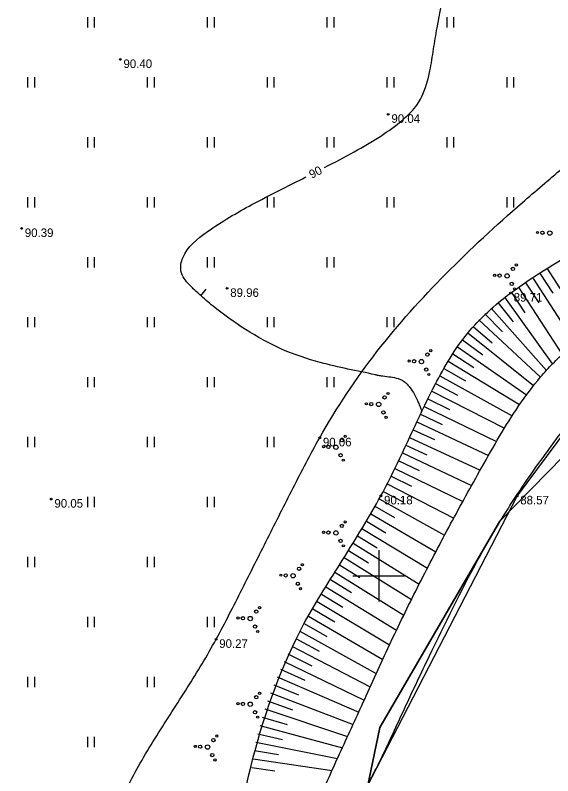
# Model space of a CAD drawing. Extents: x 635228 to 635525, y 248590 to 248800.
# Drawn here: x 635378.76 to 635410.17, y 248638.32 to 248682.72 of the extents above; entities that cross this region are included whole.
import ezdxf

# ---------------------------------------------------------------- set-up
doc = ezdxf.new("R2010")
doc.units = 0
for name, color, linetype in [('GEOD_ELEM_####_####_#', 7, 'Continuous'), ('HIDG_GRAV_####_####_#', 7, 'Continuous'), ('RAMI_UZMR_####_####_#', 7, 'Continuous'), ('RELJ_AATZ_####_TKST_#', 7, 'Continuous'), ('RELJ_ELEM_####_####_#', 7, 'Continuous'), ('RELJ_HORZ_####_TKST_#', 7, 'Continuous'), ('RELJ_HORZ_RESN_####_#', 7, 'Continuous'), ('RELJ_NOGA_####_####_#', 7, 'Continuous'), ('ROBZ_UZMR_####_####_#', 7, 'Continuous'), ('TERT_ELEM_####_####_#', 7, 'Continuous'), ('TERT_KONT_####_####_#', 7, 'Continuous')]:
    doc.layers.add(name, color=color, linetype=linetype)

msp = doc.modelspace()

# ---------------------------------------------------------------- linework, layer by layer
at = {"layer": 'GEOD_ELEM_####_####_#'}
for p, q in [((635400, 248651.5), (635400, 248650)), ((635398.5, 248650), (635400, 248650)), ((635400, 248650), (635400, 248648.5)), ((635400, 248650), (635401.5, 248650))]:
    msp.add_line(p, q, dxfattribs=at)
at = {"layer": 'HIDG_GRAV_####_####_#'}
for points in [[(635394.244, 248623.295), (635394.9074355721, 248630.6631552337), (635396.5650242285, 248636.944974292), (635397.8888882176, 248639.97580624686), (635399.2686043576, 248642.98780740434), (635400.0423829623, 248644.69884236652), (635400.835233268, 248646.3905777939), (635402.4795660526, 248649.72803076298), (635404.20443685, 248653.0239277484), (635406.0126797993, 248656.30203018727), (635407.0670223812, 248658.14081276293), (635408.1930324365, 248659.92698593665), (635409.4621962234, 248661.60192368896), (635410.172800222, 248662.37935865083), (635410.946, 248663.10700000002), (635413.0008032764, 248664.6744257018), (635415.1640977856, 248666.05372522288), (635417.3478434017, 248667.38916213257), (635419.464, 248668.825), (635422.2083511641, 248670.85354035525), (635424.965867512, 248672.86854694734), (635430.4558647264, 248676.93578902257), (635435.8049295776, 248681.1823865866), (635438.3862804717, 248683.4215875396), (635439.6466024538, 248684.57867623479), (635440.8840000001, 248685.76400000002), (635443.6087249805, 248688.6747140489), (635446.1599310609, 248691.73220612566), (635448.6719216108, 248694.81834513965), (635451.279, 248697.815), (635453.9336502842, 248700.48189136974), (635456.6811388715, 248703.07136968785), (635459.3523080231, 248705.7266631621), (635461.7780000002, 248708.59100000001), (635461.778, 248708.59100000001)], [(635396.7397638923, 248625.2320466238), (635397.9986579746, 248634.27312358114), (635398.9188026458, 248636.96227546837), (635399.5920874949, 248638.24717771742), (635399.9292604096, 248638.88899780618), (635400.2466831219, 248639.53584001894), (635401.591165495, 248642.41958219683), (635402.9524948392, 248645.2868638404), (635405.8217854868, 248650.96088254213), (635407.5583128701, 248653.91205967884), (635409.4799859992, 248656.7354955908), (635411.5283407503, 248659.48290512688), (635413.6449129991, 248662.20600313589), (635414.8182615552, 248663.6538935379), (635415.4704678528, 248664.3057478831), (635416.2076616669, 248664.85985159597), (635417.1601741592, 248665.41138033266), (635418.1313630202, 248665.91742947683), (635419.1067857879, 248666.41122678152), (635420.072, 248666.926), (635421.5645353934, 248667.7418115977), (635423.0692260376, 248668.5354410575), (635426.0762392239, 248670.12612318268), (635429.0153718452, 248671.8379856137), (635430.4352117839, 248672.78309045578), (635431.128452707, 248673.2855892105), (635431.8089561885, 248673.81096758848), (635433.1953696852, 248675.0040709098), (635434.526751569, 248676.2563297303), (635437.0226234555, 248678.92292892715), (635441.762, 248684.467), (635443.1273679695, 248686.0473501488), (635444.4678763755, 248687.6485508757), (635447.1219662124, 248690.87245996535), (635449.819572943, 248694.05663907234), (635451.2144774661, 248695.60817732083), (635452.6560000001, 248697.119), (635458.0231966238, 248702.2419696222), (635463.584, 248707.15000000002)]]:
    msp.add_spline(points, degree=3, dxfattribs=at)
at = {"layer": 'RAMI_UZMR_####_####_#'}
msp.add_lwpolyline([(635426.003, 248728.15499999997), (635436.69, 248722.584), (635450.108, 248715.45700000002), (635458.287, 248711.34600000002), (635461.7780000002, 248708.59100000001), (635463.584, 248707.15000000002), (635452.6560000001, 248697.119), (635441.762, 248684.467), (635435.9528772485, 248677.73413872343), (635432.018527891, 248673.97985762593), (635429.363741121, 248672.06248825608), (635427.0556775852, 248670.66460585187), (635420.072, 248666.926), (635415.05332695, 248664.00973325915), (635408.095218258, 248654.65947737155), (635398.6701763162, 248636.43948679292), (635398.046283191, 248634.41686083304), (635396.3166782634, 248622.87374513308), (635394.244, 248623.295), (635390.206, 248622.483), (635381.566, 248626.41900000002), (635379.918, 248627.738), (635364.657, 248634.36500000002)], dxfattribs=at)
at = {"layer": 'RELJ_ELEM_####_####_#'}
for centre in [(635384.9030000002, 248680.138), (635400.561, 248676.937), (635379.1390000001, 248670.27300000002), (635391.143, 248666.77500000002), (635407.706, 248666.499), (635396.556, 248658.053), (635380.869, 248654.47400000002), (635400.128, 248654.662), (635408.0881315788, 248654.66319467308), (635390.4990000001, 248646.29)]:
    msp.add_circle(centre, 0.05, dxfattribs=at)
at = {"layer": 'RELJ_HORZ_RESN_####_#'}
msp.add_line((635389.603708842, 248666.34758500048), (635389.9254290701, 248666.7303330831), dxfattribs=at)
for points in [[(635396.8403365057, 248673.83023932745), (635398.5699520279, 248674.74721849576), (635400.1196081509, 248675.6687893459), (635401.3847631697, 248676.59316814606), (635401.8779834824, 248677.05585311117), (635402.2608753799, 248677.51857116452), (635402.5005008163, 248677.92779942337), (635402.9962003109, 248679.47940420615), (635403.1093939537, 248680.10527297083), (635403.2077718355, 248680.73304831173), (635403.3050539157, 248681.36081107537), (635403.4149601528, 248681.98664210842), (635403.9947087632, 248684.49620174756), (635404.4941894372, 248685.58182624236), (635404.822447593, 248686.0525951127), (635405.213, 248686.464), (635405.5227683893, 248686.49325254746), (635405.8948771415, 248686.27621660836), (635406.269797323, 248686.04907236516), (635406.588, 248686.048), (635407.1331532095, 248686.47133617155), (635407.6549224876, 248686.94769115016), (635408.6437981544, 248688.02779111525), (635410.511320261, 248690.47588617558), (635412.43838879, 248692.8856225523), (635414.0718482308, 248694.36296271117), (635414.672826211, 248694.7503376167), (635415.8418707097, 248695.38166460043), (635417.0157559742, 248695.99905223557), (635418.2014500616, 248696.5900310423), (635419.4059210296, 248697.14213154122), (635424.3998390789, 248699.29274669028), (635429.4588912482, 248701.50672660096), (635434.3873884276, 248704.0886148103), (635435.2434356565, 248704.60530447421), (635437.7315604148, 248706.27775516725), (635439.1970704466, 248707.5552960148), (635439.8338858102, 248708.26101524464), (635440.1227716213, 248708.63326282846), (635440.3898668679, 248709.01944554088), (635440.6922176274, 248709.6864690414), (635440.8034457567, 248710.32396866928)], [(635399.8103222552, 248661.73440351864), (635396.5888085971, 248662.45061356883), (635394.366626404, 248663.21189688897), (635392.2183961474, 248664.3772104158), (635390.3210872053, 248665.73618021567), (635389.5218311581, 248666.4225443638), (635389.1692307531, 248666.7559414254), (635389.005897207, 248666.91875560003), (635388.851668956, 248667.07843235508), (635388.580502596, 248667.44246406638), (635388.4463483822, 248667.81035988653), (635388.5518971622, 248668.55710948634), (635389.9981689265, 248670.08999995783), (635392.5956165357, 248671.66695390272), (635394.140135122, 248672.46878284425), (635395.7493722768, 248673.27782145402)], [(635399.8103222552, 248661.73440351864), (635400.0261478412, 248661.69119462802), (635400.2502143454, 248661.65879397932), (635400.7032919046, 248661.6004776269), (635401.1299985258, 248661.5075749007), (635401.3211013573, 248661.43194128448), (635401.4089269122, 248661.38399174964), (635401.4506378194, 248661.35712915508), (635401.4709090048, 248661.3429315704), (635401.4907778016, 248661.32820623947), (635401.5807723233, 248661.25417038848), (635401.6657716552, 248661.17358317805), (635401.8221621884, 248660.99456123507), (635402.0901527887, 248660.5777731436), (635402.316788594, 248660.10674684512), (635402.4214856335, 248659.8599271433), (635402.524108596, 248659.61038721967)]]:
    msp.add_spline(points, degree=3, dxfattribs=at)
at = {"layer": 'RELJ_NOGA_####_####_#'}
for p, q in [((635409.8625812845, 248667.8947613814), (635412.2588250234, 248664.15017364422)), ((635409.0209685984, 248667.3546810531), (635411.471024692, 248663.54545166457)), ((635409.4414942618, 248667.62515871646), (635410.1688320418, 248666.49432891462)), ((635408.1819740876, 248666.81054345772), (635410.7270639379, 248662.91267369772)), ((635408.6011266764, 248667.08314360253), (635409.349370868, 248665.9286690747)), ((635407.7635920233, 248666.53676212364), (635408.5437852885, 248665.3468685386)), ((635406.954140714, 248665.95034267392), (635407.8639578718, 248664.8211765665)), ((635407.351260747, 248666.25404517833), (635410.1500262, 248662.3558521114)), ((635406.5727376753, 248665.62711643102), (635409.80308503, 248661.98852616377)), ((635406.2075806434, 248665.28563474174), (635407.2351275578, 248664.23948709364)), ((635405.858323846, 248664.92789740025), (635409.4538366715, 248661.59191409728)), ((635405.2067690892, 248664.16964832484), (635409.0494359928, 248661.09846031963)), ((635405.524936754, 248664.55531519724), (635406.6406852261, 248663.590880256)), ((635404.9031081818, 248663.7724541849), (635406.0924224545, 248662.89991224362)), ((635404.6129288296, 248663.36530031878), (635408.6437325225, 248660.56488204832)), ((635404.3355010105, 248662.94934938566), (635405.570150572, 248662.1538915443)), ((635404.0695322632, 248662.5259769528), (635408.2372923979, 248659.99157579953)), ((635403.8138835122, 248662.09628868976), (635405.0757899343, 248661.3683422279)), ((635403.5677171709, 248661.6610947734), (635407.7993181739, 248659.3316462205)), ((635403.3298174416, 248661.2213252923), (635404.6019012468, 248660.54583964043)), ((635403.0989996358, 248660.77779578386), (635407.3504701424, 248658.61333582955)), ((635402.8744485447, 248660.33105999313), (635404.1476621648, 248659.69996200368)), ((635402.6546938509, 248659.88194460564), (635406.8895087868, 248657.83840831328)), ((635402.4388250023, 248659.43094679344), (635403.7045318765, 248658.83309198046)), ((635402.2259600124, 248658.9785223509), (635406.4163447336, 248657.0153306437)), ((635402.0149403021, 248658.5252339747), (635403.2638939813, 248657.9460922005)), ((635401.8047126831, 248658.07157734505), (635405.9324446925, 248656.15963557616)), ((635401.5944158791, 248657.61795289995), (635402.8209429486, 248657.04721503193)), ((635401.3828817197, 248657.16490453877), (635405.4323121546, 248655.26686429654)), ((635401.1693375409, 248656.7128007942), (635402.371857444, 248656.14133387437)), ((635400.9523629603, 248656.26233404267), (635404.9155535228, 248654.3321689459)), ((635400.7312182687, 248655.813900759), (635401.9090420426, 248655.22776486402)), ((635400.504525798, 248655.3682482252), (635404.3841950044, 248653.35689460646)), ((635400.2715566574, 248654.92584629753), (635401.4244992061, 248654.3050520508)), ((635400.0311495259, 248654.487441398), (635403.8529759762, 248652.36697469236)), ((635399.7853263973, 248654.05204713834), (635400.927641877, 248653.39941430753)), ((635399.5353194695, 248653.61904068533), (635403.3432881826, 248651.40158427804)), ((635399.2814918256, 248653.18826239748), (635400.4250526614, 248652.50846256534)), ((635399.0245691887, 248652.7593226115), (635402.8491060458, 248650.44987386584)), ((635398.7651660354, 248652.33187755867), (635399.9195401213, 248651.6292315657)), ((635398.5036220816, 248651.90573880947), (635402.372303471, 248649.51638393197)), ((635398.2406116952, 248651.48050329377), (635399.4107770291, 248650.7538052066)), ((635397.9767011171, 248651.05582561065), (635401.9139812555, 248648.60379598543)), ((635397.7123818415, 248650.63140209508), (635398.9059240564, 248649.88809687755)), ((635397.4480625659, 248650.2069785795), (635401.4691463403, 248647.70275835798)), ((635397.1841714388, 248649.7822890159), (635398.404886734, 248649.02542891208)), ((635396.9214185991, 248649.35689421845), (635401.0455520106, 248646.82971114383)), ((635396.6603968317, 248648.9304351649), (635397.912700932, 248648.16809362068)), ((635396.4015071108, 248648.5026791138), (635400.6297667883, 248645.95755458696)), ((635396.1453199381, 248648.07329945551), (635397.4305159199, 248647.310845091)), ((635395.8924346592, 248647.64196741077), (635400.2341078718, 248645.11319087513)), ((635395.6434494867, 248647.2083733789), (635396.9638008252, 248646.45688244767)), ((635395.3987285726, 248646.77235914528), (635399.8578038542, 248644.2959553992)), ((635395.1592577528, 248646.33343967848), (635396.515748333, 248645.60547558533)), ((635394.9254901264, 248645.89145760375), (635399.5018986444, 248643.51020417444)), ((635394.6980998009, 248645.44616223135), (635396.0872204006, 248644.74903596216)), ((635394.4778019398, 248644.99731716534), (635399.1602100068, 248642.7450621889)), ((635394.2652962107, 248644.54473257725), (635395.6844547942, 248643.8953250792)), ((635394.0612347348, 248644.08827897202), (635398.8356996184, 248642.02842921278)), ((635393.8665220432, 248643.6277600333), (635395.3065858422, 248643.03745984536)), ((635393.6819048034, 248643.1631041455), (635398.5056898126, 248641.3108477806)), ((635393.5081369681, 248642.69428455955), (635394.9604265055, 248642.1775982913)), ((635393.3459706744, 248642.2213274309), (635398.1849883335, 248640.61727893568)), ((635393.1963722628, 248641.74424806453), (635394.6486151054, 248641.31022044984)), ((635393.0598719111, 248641.26325946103), (635397.8804933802, 248639.9573297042)), ((635392.9373423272, 248640.77852435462), (635394.378894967, 248640.44188390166)), ((635392.8295318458, 248640.2903059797), (635397.5937404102, 248639.32973477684)), ((635392.736983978, 248639.79896699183), (635394.1504539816, 248639.56165782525)), ((635392.6599254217, 248639.30495737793), (635397.2803028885, 248638.63095366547)), ((635392.5877511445, 248638.81019392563), (635393.9330397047, 248638.61394816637))]:
    msp.add_line(p, q, dxfattribs=at)
msp.add_spline([(635390.206, 248622.483), (635392.6761559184, 248639.41621940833), (635395.6724652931, 248647.2597307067), (635397.9131924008, 248650.95381667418), (635399.048256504, 248652.79837067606), (635400.128, 248654.662), (635400.9493075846, 248656.2558432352), (635403.3016292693, 248661.16811378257), (635405.1862207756, 248664.14373210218), (635407.706, 248666.499), (635412.1610828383, 248669.3503906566), (635416.627, 248672.168), (635424.6828055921, 248677.31078055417), (635432.728, 248682.47600000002), (635436.7060689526, 248685.70428438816), (635438.5008534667, 248687.5575466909), (635440.2150000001, 248689.48700000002), (635442.5291182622, 248692.3528262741), (635444.7219287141, 248695.30565037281), (635446.9190248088, 248698.24939928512), (635449.246, 248701.08800000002), (635451.3600052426, 248703.48451832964), (635453.4937434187, 248705.86484004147), (635457.9500000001, 248710.44), (635458.6576193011, 248711.10744185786)], degree=3, dxfattribs=at)
at = {"layer": 'ROBZ_UZMR_####_####_#'}
msp.add_lwpolyline([(635325.5420000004, 248659.74000000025), (635329.6529999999, 248676.3660000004), (635327.79, 248676.82799999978), (635337.4600999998, 248688.65990000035), (635343.3430000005, 248703.1199999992), (635360.483, 248762.61500000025), (635458.6069999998, 248711.13399999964), (635465.4589999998, 248707.53900000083), (635439.4570000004, 248681.03800000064), (635424.5429999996, 248670.01400000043), (635420.9790000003, 248667.37900000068), (635407.0700000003, 248653.17999999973), (635400.0669999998, 248641.1490000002), (635395.1619999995, 248617.53900000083), (635389.0310000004, 248621.06200000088), (635375.858, 248629.11500000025)], close=True, dxfattribs=at)
msp.add_lwpolyline([(635432.3373132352, 248596.18186087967), (635395.1619999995, 248617.53900000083), (635400.0669999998, 248641.1490000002), (635407.0700000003, 248653.17999999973), (635420.9790000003, 248667.37900000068), (635424.5429999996, 248670.01400000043), (635430.9589999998, 248667.77300000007), (635522.3373132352, 248635.85405923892)], dxfattribs=at)
at = {"layer": 'TERT_ELEM_####_####_#'}
for p, q in [((635383, 248682), (635383, 248682.6)), ((635383.4, 248682), (635383.4, 248682.6)), ((635390, 248682), (635390, 248682.6)), ((635390.4, 248682), (635390.4, 248682.6)), ((635397, 248682), (635397, 248682.6)), ((635397.4, 248682), (635397.4, 248682.6)), ((635404, 248682), (635404, 248682.6)), ((635404.4, 248682), (635404.4, 248682.6)), ((635379.5, 248678.5), (635379.5, 248679.1)), ((635379.9, 248678.5), (635379.9, 248679.1)), ((635386.5, 248678.5), (635386.5, 248679.1)), ((635386.9, 248678.5), (635386.9, 248679.1)), ((635393.5, 248678.5), (635393.5, 248679.1)), ((635393.9, 248678.5), (635393.9, 248679.1)), ((635400.5, 248678.5), (635400.5, 248679.1)), ((635400.9, 248678.5), (635400.9, 248679.1)), ((635407.5, 248678.5), (635407.5, 248679.1)), ((635407.9, 248678.5), (635407.9, 248679.1)), ((635383, 248675), (635383, 248675.6)), ((635383.4, 248675), (635383.4, 248675.6)), ((635390, 248675), (635390, 248675.6)), ((635390.4, 248675), (635390.4, 248675.6)), ((635397, 248675), (635397, 248675.6)), ((635397.4, 248675), (635397.4, 248675.6)), ((635404, 248675), (635404, 248675.6)), ((635404.4, 248675), (635404.4, 248675.6)), ((635379.5, 248671.5), (635379.5, 248672.1)), ((635379.9, 248671.5), (635379.9, 248672.1)), ((635386.5, 248671.5), (635386.5, 248672.1)), ((635386.9, 248671.5), (635386.9, 248672.1)), ((635393.5, 248671.5), (635393.5, 248672.1)), ((635393.9, 248671.5), (635393.9, 248672.1)), ((635400.5, 248671.5), (635400.5, 248672.1)), ((635400.9, 248671.5), (635400.9, 248672.1)), ((635407.5, 248671.5), (635407.5, 248672.1)), ((635407.9, 248671.5), (635407.9, 248672.1)), ((635383, 248668), (635383, 248668.6)), ((635383.4, 248668), (635383.4, 248668.6)), ((635390, 248668), (635390, 248668.6)), ((635390.4, 248668), (635390.4, 248668.6)), ((635397, 248668), (635397, 248668.6)), ((635397.4, 248668), (635397.4, 248668.6)), ((635379.5, 248664.5), (635379.5, 248665.1)), ((635379.9, 248664.5), (635379.9, 248665.1)), ((635386.5, 248664.5), (635386.5, 248665.1)), ((635386.9, 248664.5), (635386.9, 248665.1)), ((635393.5, 248664.5), (635393.5, 248665.1)), ((635393.9, 248664.5), (635393.9, 248665.1)), ((635400.5, 248664.5), (635400.5, 248665.1)), ((635400.9, 248664.5), (635400.9, 248665.1)), ((635383, 248661), (635383, 248661.6)), ((635383.4, 248661), (635383.4, 248661.6)), ((635390, 248661), (635390, 248661.6)), ((635390.4, 248661), (635390.4, 248661.6)), ((635397, 248661), (635397, 248661.6)), ((635397.4, 248661), (635397.4, 248661.6)), ((635379.5, 248657.5), (635379.5, 248658.1)), ((635379.9, 248657.5), (635379.9, 248658.1)), ((635386.5, 248657.5), (635386.5, 248658.1)), ((635386.9, 248657.5), (635386.9, 248658.1)), ((635393.5, 248657.5), (635393.5, 248658.1)), ((635393.9, 248657.5), (635393.9, 248658.1)), ((635383, 248654), (635383, 248654.6)), ((635383.4, 248654), (635383.4, 248654.6)), ((635390, 248654), (635390, 248654.6)), ((635390.4, 248654), (635390.4, 248654.6)), ((635379.5, 248650.5), (635379.5, 248651.1)), ((635379.9, 248650.5), (635379.9, 248651.1)), ((635386.5, 248650.5), (635386.5, 248651.1)), ((635386.9, 248650.5), (635386.9, 248651.1)), ((635383, 248647), (635383, 248647.6)), ((635383.4, 248647), (635383.4, 248647.6)), ((635390, 248647), (635390, 248647.6)), ((635390.4, 248647), (635390.4, 248647.6)), ((635379.5, 248643.5), (635379.5, 248644.1)), ((635379.9, 248643.5), (635379.9, 248644.1)), ((635386.5, 248643.5), (635386.5, 248644.1)), ((635386.9, 248643.5), (635386.9, 248644.1)), ((635383, 248640), (635383, 248640.6)), ((635383.4, 248640), (635383.4, 248640.6))]:
    msp.add_line(p, q, dxfattribs=at)
for centre, radius in [((635409.2816, 248670.03423999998), 0.06400000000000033), ((635409.56608, 248670.02079999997), 0.09600000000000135), ((635410, 248670), 0.12800000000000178), ((635408.044, 248668.13935999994), 0.06400000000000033), ((635407.8475200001, 248667.90767999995), 0.09600000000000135), ((635406.7816, 248667.53423999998), 0.06400000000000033), ((635407.06608, 248667.52079999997), 0.09600000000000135), ((635407.5, 248667.5), 0.12800000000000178), ((635407.77648, 248667.03311999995), 0.09600000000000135), ((635407.93392, 248666.74383999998), 0.06400000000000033), ((635402.8475200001, 248662.90767999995), 0.09600000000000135), ((635403.044, 248663.13935999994), 0.06400000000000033), ((635401.7816, 248662.53423999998), 0.06400000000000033), ((635402.06608, 248662.52079999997), 0.09600000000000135), ((635402.5, 248662.5), 0.12800000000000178), ((635402.77648, 248662.03311999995), 0.09600000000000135), ((635402.93392, 248661.74383999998), 0.06400000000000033), ((635400.544, 248660.63935999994), 0.06400000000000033), ((635400.3475200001, 248660.40767999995), 0.09600000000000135), ((635399.2816, 248660.03423999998), 0.06400000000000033), ((635399.56608, 248660.02079999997), 0.09600000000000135), ((635400, 248660), 0.12800000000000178), ((635400.27648, 248659.53311999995), 0.09600000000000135), ((635400.43392, 248659.24383999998), 0.06400000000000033), ((635397.8475200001, 248657.90767999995), 0.09600000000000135), ((635398.044, 248658.13935999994), 0.06400000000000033), ((635396.7816, 248657.53423999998), 0.06400000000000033), ((635397.06608, 248657.52079999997), 0.09600000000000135), ((635397.5, 248657.5), 0.12800000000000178), ((635397.77648, 248657.03311999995), 0.09600000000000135), ((635397.93392, 248656.74383999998), 0.06400000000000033), ((635398.044, 248653.13935999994), 0.06400000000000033), ((635397.06608, 248652.52079999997), 0.09600000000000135), ((635397.5, 248652.5), 0.12800000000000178), ((635397.8475200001, 248652.90767999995), 0.09600000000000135), ((635396.7816, 248652.53423999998), 0.06400000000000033), ((635397.77648, 248652.03311999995), 0.09600000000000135), ((635397.93392, 248651.74383999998), 0.06400000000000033), ((635395.3475200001, 248650.40767999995), 0.09600000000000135), ((635395.544, 248650.63935999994), 0.06400000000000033), ((635394.2816, 248650.03423999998), 0.06400000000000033), ((635394.56608, 248650.02079999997), 0.09600000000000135), ((635395, 248650), 0.12800000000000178), ((635395.27648, 248649.53311999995), 0.09600000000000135), ((635395.43392, 248649.24383999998), 0.06400000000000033), ((635393.044, 248648.13935999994), 0.06400000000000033), ((635392.8475200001, 248647.90767999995), 0.09600000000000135), ((635391.7816, 248647.53423999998), 0.06400000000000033), ((635392.06608, 248647.52079999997), 0.09600000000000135), ((635392.5, 248647.5), 0.12800000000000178), ((635392.77648, 248647.03311999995), 0.09600000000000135), ((635392.93392, 248646.74383999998), 0.06400000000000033), ((635392.8475200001, 248642.90767999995), 0.09600000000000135), ((635393.044, 248643.13935999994), 0.06400000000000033), ((635391.7816, 248642.53423999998), 0.06400000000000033), ((635392.06608, 248642.52079999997), 0.09600000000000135), ((635392.5, 248642.5), 0.12800000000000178), ((635392.77648, 248642.03311999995), 0.09600000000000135), ((635392.93392, 248641.74383999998), 0.06400000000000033), ((635390.544, 248640.63935999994), 0.06400000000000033), ((635390.3475200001, 248640.40767999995), 0.09600000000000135), ((635389.2816, 248640.03423999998), 0.06400000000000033), ((635389.56608, 248640.02079999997), 0.09600000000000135), ((635390, 248640), 0.12800000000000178), ((635390.27648, 248639.53311999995), 0.09600000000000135), ((635390.43392, 248639.24383999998), 0.06400000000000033)]:
    msp.add_circle(centre, radius, dxfattribs=at)
at = {"layer": 'TERT_KONT_####_####_#'}
for points in [[(635347.944, 248675.14), (635353.9686253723, 248676.31675870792), (635361.5476815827, 248680.8919163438), (635362.735, 248687.69400000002), (635367.699, 248695.07200000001), (635365.801, 248699.25900000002), (635373.4, 248711.674), (635374.8350000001, 248703.88100000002), (635382.868, 248697.46300000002), (635386.0850000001, 248703.415)], [(635381.566, 248626.41900000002), (635384.141, 248634.765), (635385.389202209, 248637.7914590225), (635387.0292419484, 248640.6516206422), (635388.8146607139, 248643.4497219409), (635389.6848689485, 248644.8580740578), (635390.4990000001, 248646.29), (635392.0226550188, 248649.21918285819), (635393.5071185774, 248652.1702394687), (635395.0017728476, 248655.12192634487), (635396.556, 248658.053), (635399.9011134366, 248663.08488427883), (635403.9259848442, 248667.61643358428), (635408.395257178, 248671.78623589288), (635410.7229946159, 248673.7787906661), (635413.0735733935, 248675.7328791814), (635414.4692599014, 248676.62068389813), (635415.9938205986, 248677.30794837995), (635417.5018643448, 248678.0054584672), (635418.848, 248678.924), (635420.219040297, 248680.28079949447), (635421.4913245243, 248681.74225536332), (635423.8682567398, 248684.84208090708), (635426.2360605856, 248687.94936599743), (635428.1606833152, 248690.11983046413), (635428.8520000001, 248690.79), (635429.5317929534, 248691.3720486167), (635430.2428233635, 248691.92597447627), (635430.954192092, 248692.47941309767), (635431.635, 248693.06), (635432.7520114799, 248694.18745503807), (635433.7815998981, 248695.39485218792), (635435.7079899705, 248697.94525714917), (635437.6731350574, 248700.50278353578), (635438.7511672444, 248701.71908246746), (635439.936, 248702.85900000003), (635442.1191491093, 248704.47891720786), (635444.4652000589, 248705.76616705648), (635446.9243060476, 248706.83607415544), (635448.1806775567, 248707.32556311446), (635449.4466202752, 248707.80396311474), (635450.5789798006, 248708.1275799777), (635451.7602437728, 248708.30057270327), (635452.9245409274, 248708.35276985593), (635454.0060000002, 248708.314), (635454.3355621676, 248708.1390314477), (635454.6423695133, 248707.79518323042), (635454.9454921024, 248707.47799339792), (635455.2640000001, 248707.383), (635455.8819855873, 248707.57371461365), (635456.5298319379, 248707.8540188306), (635457.157262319, 248708.21606363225), (635457.714, 248708.652), (635459.5420464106, 248710.35555231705)]]:
    msp.add_spline(points, degree=3, dxfattribs=at)

# ---------------------------------------------------------------- texts
at = {"layer": 'RELJ_AATZ_####_TKST_#'}
for s, p in [(' 90.40', (635384.9030000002, 248679.638)), (' 90.04', (635400.561, 248676.437)), (' 90.39', (635379.1390000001, 248669.77300000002)), (' 89.96', (635391.143, 248666.27500000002)), (' 89.71', (635407.706, 248665.999)), (' 90.06', (635396.556, 248657.553)), (' 90.05', (635380.869, 248653.97400000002)), (' 90.18', (635400.128, 248654.162)), (' 88.57', (635408.0881315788, 248654.16319467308)), (' 90.27', (635390.4990000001, 248645.79))]:
    msp.add_text(s, height=0.5, dxfattribs=at).set_placement(p)
at = {"layer": 'RELJ_HORZ_####_TKST_#'}
msp.add_text('90', height=0.5, rotation=26.835332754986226, dxfattribs=at).set_placement((635396.0857446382, 248673.1667347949))

doc.saveas('drawing.dxf')
